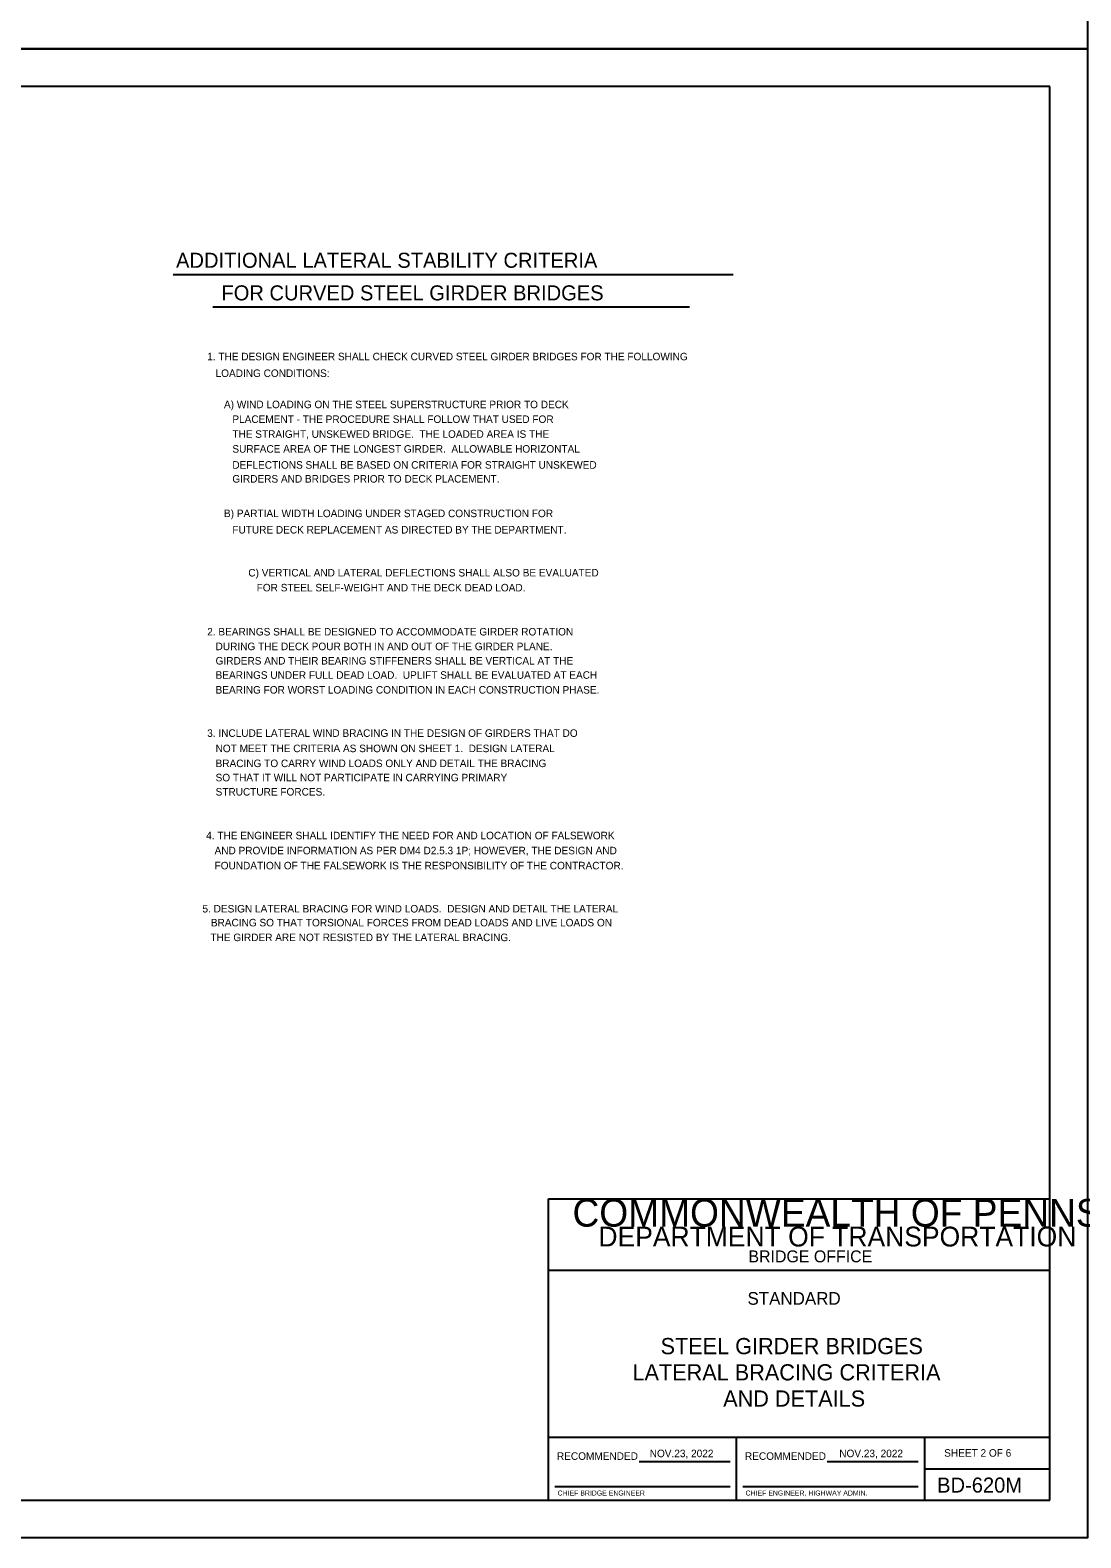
# Model space of a CAD drawing. Extents: x 30 to 2621, y -33 to 1155.
# Drawn here: x 450 to 869, y -33 to 568 of the extents above; entities that cross this region are included whole.
import ezdxf

# ---------------------------------------------------------------- set-up
doc = ezdxf.new("R2010")
doc.units = 0
for name, color, linetype in [('1', 7, 'Continuous'), ('2', 7, 'Continuous'), ('PLT-BNDY', 7, 'Continuous'), ('SIGNATORY TITLES', 7, 'Continuous')]:
    doc.layers.add(name, color=color, linetype=linetype)

msp = doc.modelspace()

# ---------------------------------------------------------------- linework, layer by layer
at = {"layer": '1'}
for p, q in [((856.5, 546), (70.5, 546)), ((856.5, -18), (856.5, 546)), ((730.08, 470.89), (506.7, 470.89)), ((712.65, 457.98), (522.53, 457.98)), ((656.5, -18), (656.5, 102.23)), ((656.5, 102.23), (856.5, 102.23)), ((656.5, 73.75), (856.5, 73.75)), ((856.5, 7), (656.5, 7)), ((731.5, -18), (731.5, 7)), ((806.5, 7), (806.5, -18)), ((692.59, -2.5), (729, -2.5)), ((767.59, -2.5), (804, -2.5)), ((806.5, -5.5), (856.5, -5.5)), ((70.5, -18), (856.5, -18)), ((659, -12.5), (729, -12.5)), ((734, -12.5), (804, -12.5))]:
    msp.add_line(p, q, dxfattribs=at)
at = {"layer": '2'}
msp.add_line((856.5, 7), (656.5, 7), dxfattribs=at)
at = {"layer": 'PLT-BNDY'}
for points in [[(30.5, 1155), (871.5, 1155), (871.5, 561), (30.5, 561)], [(30.5, 561), (871.5, 561), (871.5, -33), (30.5, -33)]]:
    msp.add_lwpolyline(points, close=True, dxfattribs=at)

# ---------------------------------------------------------------- texts
at = {"layer": '1'}
for s, height, p in [('ADDITIONAL LATERAL STABILITY CRITERIA', 6, (507.87, 473.69)), ('FOR CURVED STEEL GIRDER BRIDGES', 6, (525.98, 460.69)), (' 1. THE DESIGN ENGINEER SHALL CHECK CURVED STEEL GIRDER BRIDGES FOR THE FOLLOWING', 3, (519.19, 436.79)), ('    LOADING CONDITIONS:', 3, (519.19, 430.14)), ('       A) WIND LOADING ON THE STEEL SUPERSTRUCTURE PRIOR TO DECK', 3, (519.19, 417.68)), ('          PLACEMENT - THE PROCEDURE SHALL FOLLOW THAT USED FOR ', 3, (519.19, 411.8)), ('          THE STRAIGHT, UNSKEWED BRIDGE.  THE LOADED AREA IS THE', 3, (519.19, 405.86)), ('          SURFACE AREA OF THE LONGEST GIRDER.  ALLOWABLE HORIZONTAL', 3, (519.19, 399.94)), ('          GIRDERS AND BRIDGES PRIOR TO DECK PLACEMENT.', 3, (519.19, 388)), ('          DEFLECTIONS SHALL BE BASED ON CRITERIA FOR STRAIGHT UNSKEWED', 3, (519.19, 393.55)), ('       B) PARTIAL WIDTH LOADING UNDER STAGED CONSTRUCTION FOR', 3, (519.19, 374.21)), ('          FUTURE DECK REPLACEMENT AS DIRECTED BY THE DEPARTMENT.', 3, (519.19, 367.68)), (' C) VERTICAL AND LATERAL DEFLECTIONS SHALL ALSO BE EVALUATED', 3, (535.59, 350.54)), ('    FOR STEEL SELF-WEIGHT AND THE DECK DEAD LOAD.', 3, (535.59, 344.59)), (' 2. BEARINGS SHALL BE DESIGNED TO ACCOMMODATE GIRDER ROTATION', 3, (519.19, 327)), ('    DURING THE DECK POUR BOTH IN AND OUT OF THE GIRDER PLANE.', 3, (519.19, 321.14)), ('    GIRDERS AND THEIR BEARING STIFFENERS SHALL BE VERTICAL AT THE', 3, (519.19, 315.41)), ('    BEARINGS UNDER FULL DEAD LOAD.  UPLIFT SHALL BE EVALUATED AT EACH', 3, (519.19, 309.73)), ('    BEARING FOR WORST LOADING CONDITION IN EACH CONSTRUCTION PHASE.', 3, (519.19, 303.82)), (' 3. INCLUDE LATERAL WIND BRACING IN THE DESIGN OF GIRDERS THAT DO', 3, (519.19, 286.56)), ('    NOT MEET THE CRITERIA AS SHOWN ON SHEET 1.  DESIGN LATERAL', 3, (519.19, 280.45)), ('    BRACING TO CARRY WIND LOADS ONLY AND DETAIL THE BRACING', 3, (519.19, 274.49)), ('    SO THAT IT WILL NOT PARTICIPATE IN CARRYING PRIMARY', 3, (519.19, 268.82)), ('    STRUCTURE FORCES.', 3, (519.19, 263.14)), ('4. THE ENGINEER SHALL IDENTIFY THE NEED FOR AND LOCATION OF FALSEWORK', 3, (519.89, 245.7)), ('   AND PROVIDE INFORMATION AS PER DM4 D2.5.3 1P; HOWEVER, THE DESIGN AND', 3, (519.89, 239.7)), ('   FOUNDATION OF THE FALSEWORK IS THE RESPONSIBILITY OF THE CONTRACTOR.', 3, (519.89, 233.7)), (' 5. DESIGN LATERAL BRACING FOR WIND LOADS.  DESIGN AND DETAIL THE LATERAL', 3, (517.3, 216.49)), ('    BRACING SO THAT TORSIONAL FORCES FROM DEAD LOADS AND LIVE LOADS ON', 3, (517.3, 210.95)), ('    THE GIRDER ARE NOT RESISTED BY THE LATERAL BRACING.', 3, (517.13, 205.06)), ('COMMONWEALTH OF PENNSYLVANIA', 11.0789, (666.03, 91.15)), ('COMMONWEALTH OF PENNSYLVANIA', 11.0789, (666.03, 91.15)), ('DEPARTMENT OF TRANSPORTATION', 7.8962, (676.38, 83.25)), ('DEPARTMENT OF TRANSPORTATION', 7.8962, (676.38, 83.25)), ('BRIDGE OFFICE', 4.7495, (736.22, 76.92)), ('STANDARD', 5.055, (735.84, 60)), ('STEEL GIRDER BRIDGES', 6.4601, (701.17, 40.27)), ('LATERAL BRACING CRITERIA', 6.4601, (689.96, 29.81)), ('AND DETAILS', 6.4601, (726.15, 19.35)), ('RECOMMENDED', 3, (659.83, -1.88)), ('RECOMMENDED', 3, (734.83, -1.88)), ('SHEET 2 OF 6', 3, (814.33, -0.62)), ('BD-620M', 6, (811.5, -14.94))]:
    msp.add_text(s, height=height, dxfattribs=at).set_placement(p)
at = {"layer": 'SIGNATORY TITLES'}
for s, height, p in [('NOV.23, 2022', 3, (696.84, -0.82)), ('NOV.23, 2022', 3, (772.46, -0.82)), ('CHIEF BRIDGE ENGINEER', 2, (660.09, -16.12)), ('CHIEF ENGINEER, HIGHWAY ADMIN.', 2, (735.09, -16.12))]:
    msp.add_text(s, height=height, dxfattribs=at).set_placement(p)

doc.saveas('drawing.dxf')
